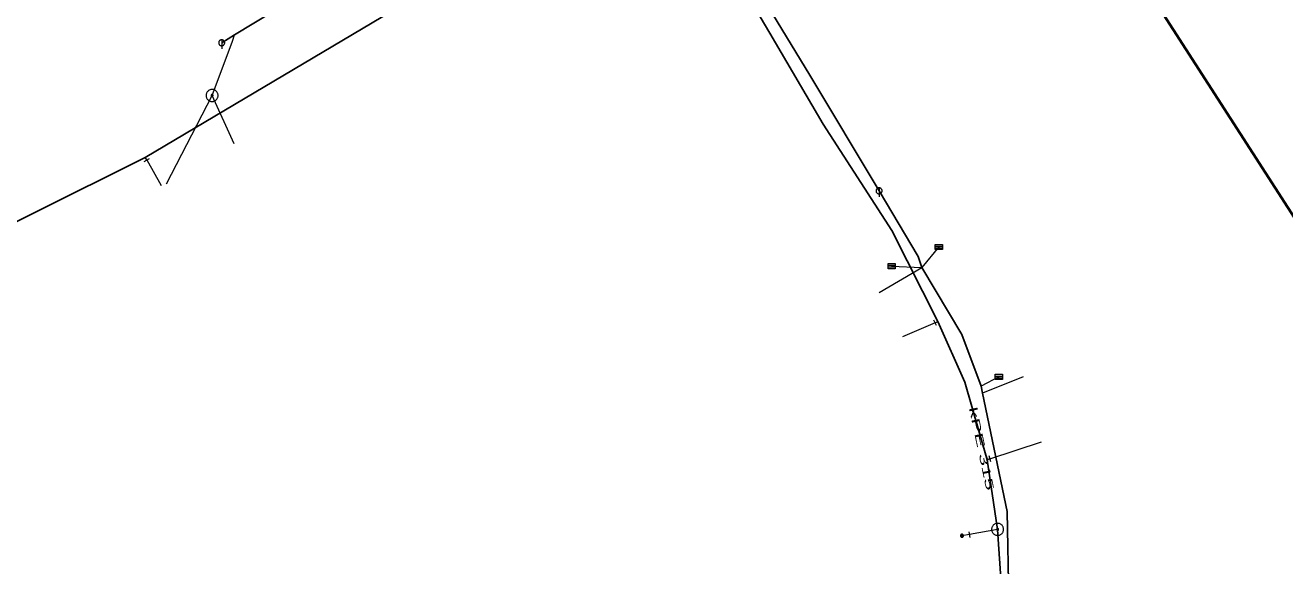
# Model space of a CAD drawing. Extents: x -687468 to -685917, y -974192 to -973456.
# Drawn here: x -686251.8 to -686146.9, y -973639.5 to -973594.5 of the extents above; entities that cross this region are included whole.
import ezdxf
from ezdxf.enums import TextEntityAlignment as Align

# ---------------------------------------------------------------- set-up
doc = ezdxf.new("R2010")
doc.units = 0
doc.header["$LTSCALE"] = 0.27
for name, color, linetype, lineweight in [('1', 7, 'Continuous', 13), ('11', 7, 'Continuous', 13), ('13', 7, 'Continuous', 13), ('14', 7, 'Continuous', 25), ('17', 7, 'Continuous', 25), ('22', 7, 'Continuous', 13), ('31', 7, 'Continuous', 13), ('34', 7, 'Continuous', 13), ('47', 7, 'Continuous', 13), ('9', 7, 'Continuous', 13)]:
    doc.layers.add(name, color=color, linetype=linetype, lineweight=lineweight)

msp = doc.modelspace()

# ---------------------------------------------------------------- linework, layer by layer
at = {"layer": '11'}
for p, q in [((-686240.079, -973607.739), (-686236.269, -973600.389)), ((-686234.43, -973604.42), (-686236.269, -973600.389)), ((-686175.71, -973613), (-686177.129, -973614.719)), ((-686179.649, -973614.59), (-686177.129, -973614.719)), ((-686180.69, -973616.789), (-686177.129, -973614.719)), ((-686170.719, -973623.82), (-686172.17, -973624.579)), ((-686168.67, -973623.809), (-686172.07, -973625.16))]:
    msp.add_line(p, q, dxfattribs=at)
msp.add_lwpolyline([(-686236.269, -973600.389), (-686234.579, -973595.86), (-686234.388, -973595.344)], dxfattribs=at)
at = {"layer": '13'}
for p, q in [((-686241.711, -973605.754), (-686240.51, -973607.879)), ((-686176.022, -973619.312), (-686178.73, -973620.48)), ((-686171.449, -973630.64), (-686167.149, -973629.219))]:
    msp.add_line(p, q, dxfattribs=at)
at = {"layer": '14', "lineweight": 13}
for p, q in [((-686241.711, -973605.754), (-686241.84, -973605.539)), ((-686176.022, -973619.312), (-686175.8, -973619.199)), ((-686171.449, -973630.64), (-686171.69, -973630.71)), ((-686170.809, -973636.51), (-686173.14, -973636.949)), ((-686173.14, -973636.949), (-686173.779, -973637.039))]:
    msp.add_line(p, q, dxfattribs=at)
at = {"layer": '14'}
for points in [[(-686235.469, -973596), (-686234.388, -973595.344), (-686219.48, -973586.316), (-686219.052, -973586.057), (-686200.73, -973574.96), (-686199.012, -973577.618)], [(-686200.73, -973574.96), (-686195.82, -973583.199), (-686189.969, -973592.96), (-686186.46, -973598.699), (-686180.69, -973608.329)], [(-686180.69, -973608.329), (-686177.42, -973613.78), (-686177.129, -973614.719), (-686173.8, -973620.3), (-686172.17, -973624.579), (-686172.07, -973625.16), (-686170.02, -973635.02), (-686169.879, -973642.359)]]:
    msp.add_lwpolyline(points, dxfattribs=at)
at = {"layer": '17', "lineweight": 35}
msp.add_lwpolyline([(-686160.425, -973551.891), (-686169.469, -973574.282), (-686122.999, -973646.384), (-686098.932, -973712.353), (-686089.329, -973782.048), (-686297.791, -974027.806), (-686326.807, -974076.614), (-686379.703, -974100.561), (-686411.584, -974111.413)], dxfattribs=at)
at = {"layer": '17'}
for points in [[(-686198.399, -973580.199), (-686194.62, -973587), (-686189.789, -973595.21), (-686185.35, -973602.78), (-686179.62, -973611.64), (-686175.8, -973619.199), (-686173.53, -973624.27), (-686171.69, -973630.71), (-686170.809, -973636.51)], [(-686215.348, -973589.807), (-686215.489, -973589.889), (-686241.84, -973605.539), (-686260.53, -973614.85), (-686290.159, -973621.799)], [(-686170.809, -973636.51), (-686170.55, -973640.579), (-686170.53, -973645.19), (-686170.789, -973648.34), (-686171.35, -973651.629), (-686172.64, -973657.55), (-686173.609, -973662.11), (-686175.16, -973665.03), (-686175.91, -973666.62), (-686176.82, -973668.219), (-686179.17, -973671.98), (-686179.739, -973673.309), (-686180.87, -973675.1), (-686183.76, -973679.21), (-686188.889, -973684.979)]]:
    msp.add_lwpolyline(points, dxfattribs=at)
at = {"layer": '22'}
for p, q in [((-686235.468, -973595.748), (-686235.469, -973596.492)), ((-686180.689, -973608.077), (-686180.69, -973608.821)), ((-686176.005, -973612.929), (-686175.407, -973612.929)), ((-686176.005, -973613.075), (-686175.407, -973613.075)), ((-686179.944, -973614.519), (-686179.346, -973614.519)), ((-686179.944, -973614.664), (-686179.346, -973614.664)), ((-686171.014, -973623.749), (-686170.416, -973623.749)), ((-686171.014, -973623.894), (-686170.416, -973623.894))]:
    msp.add_line(p, q, dxfattribs=at)
for points in [[(-686235.217, -973596), (-686235.218, -973595.974), (-686235.222, -973595.948), (-686235.228, -973595.922), (-686235.238, -973595.898), (-686235.25, -973595.874), (-686235.264, -973595.852), (-686235.281, -973595.831), (-686235.299, -973595.813), (-686235.32, -973595.796), (-686235.342, -973595.782), (-686235.366, -973595.77), (-686235.39, -973595.76), (-686235.416, -973595.754), (-686235.442, -973595.75), (-686235.468, -973595.748), (-686235.494, -973595.749), (-686235.52, -973595.753), (-686235.546, -973595.759), (-686235.571, -973595.769), (-686235.594, -973595.781), (-686235.616, -973595.795), (-686235.637, -973595.812), (-686235.655, -973595.83), (-686235.672, -973595.851), (-686235.686, -973595.873), (-686235.698, -973595.897), (-686235.708, -973595.921), (-686235.715, -973595.947), (-686235.719, -973595.973), (-686235.721, -973595.999), (-686235.72, -973596.025), (-686235.716, -973596.051), (-686235.709, -973596.077), (-686235.699, -973596.102), (-686235.687, -973596.125), (-686235.673, -973596.147), (-686235.656, -973596.168), (-686235.638, -973596.186), (-686235.617, -973596.203), (-686235.595, -973596.217), (-686235.572, -973596.229), (-686235.547, -973596.239), (-686235.521, -973596.246), (-686235.495, -973596.25), (-686235.469, -973596.252), (-686235.443, -973596.251), (-686235.417, -973596.247), (-686235.391, -973596.24), (-686235.367, -973596.23), (-686235.343, -973596.218), (-686235.321, -973596.204), (-686235.3, -973596.187), (-686235.282, -973596.169), (-686235.265, -973596.148), (-686235.251, -973596.126), (-686235.239, -973596.103), (-686235.229, -973596.078), (-686235.223, -973596.052), (-686235.219, -973596.026)], [(-686180.438, -973608.329), (-686180.439, -973608.303), (-686180.443, -973608.277), (-686180.449, -973608.251), (-686180.459, -973608.227), (-686180.471, -973608.203), (-686180.485, -973608.181), (-686180.502, -973608.16), (-686180.52, -973608.142), (-686180.541, -973608.125), (-686180.563, -973608.111), (-686180.587, -973608.099), (-686180.611, -973608.089), (-686180.637, -973608.083), (-686180.663, -973608.079), (-686180.689, -973608.077), (-686180.715, -973608.078), (-686180.741, -973608.082), (-686180.767, -973608.088), (-686180.792, -973608.098), (-686180.815, -973608.11), (-686180.837, -973608.124), (-686180.858, -973608.141), (-686180.876, -973608.159), (-686180.893, -973608.18), (-686180.907, -973608.202), (-686180.919, -973608.226), (-686180.929, -973608.25), (-686180.936, -973608.276), (-686180.94, -973608.302), (-686180.941, -973608.328), (-686180.941, -973608.354), (-686180.937, -973608.38), (-686180.93, -973608.406), (-686180.92, -973608.431), (-686180.908, -973608.454), (-686180.894, -973608.476), (-686180.877, -973608.497), (-686180.859, -973608.515), (-686180.838, -973608.532), (-686180.816, -973608.546), (-686180.793, -973608.558), (-686180.768, -973608.568), (-686180.742, -973608.575), (-686180.716, -973608.579), (-686180.69, -973608.581), (-686180.664, -973608.58), (-686180.638, -973608.576), (-686180.612, -973608.569), (-686180.588, -973608.559), (-686180.564, -973608.547), (-686180.542, -973608.533), (-686180.521, -973608.516), (-686180.503, -973608.498), (-686180.486, -973608.477), (-686180.472, -973608.455), (-686180.46, -973608.432), (-686180.45, -973608.407), (-686180.444, -973608.381), (-686180.44, -973608.355)], [(-686176.005, -973612.783), (-686175.407, -973612.783), (-686175.407, -973613.22), (-686176.005, -973613.22)], [(-686179.944, -973614.373), (-686179.346, -973614.373), (-686179.346, -973614.809), (-686179.944, -973614.809)], [(-686171.014, -973623.603), (-686170.416, -973623.603), (-686170.416, -973624.039), (-686171.014, -973624.039)]]:
    msp.add_lwpolyline(points, close=True, dxfattribs=at)
at = {"layer": '31'}
for points in [[(-686235.769, -973600.389), (-686235.772, -973600.337), (-686235.78, -973600.284), (-686235.794, -973600.235), (-686235.811, -973600.186), (-686235.836, -973600.139), (-686235.865, -973600.095), (-686235.897, -973600.054), (-686235.934, -973600.017), (-686235.975, -973599.985), (-686236.019, -973599.956), (-686236.066, -973599.931), (-686236.115, -973599.914), (-686236.164, -973599.9), (-686236.217, -973599.892), (-686236.269, -973599.889), (-686236.321, -973599.892), (-686236.373, -973599.9), (-686236.424, -973599.914), (-686236.472, -973599.931), (-686236.519, -973599.956), (-686236.563, -973599.985), (-686236.603, -973600.017), (-686236.641, -973600.054), (-686236.674, -973600.095), (-686236.701, -973600.139), (-686236.726, -973600.186), (-686236.745, -973600.235), (-686236.757, -973600.284), (-686236.766, -973600.337), (-686236.769, -973600.389), (-686236.766, -973600.441), (-686236.757, -973600.493), (-686236.745, -973600.544), (-686236.726, -973600.592), (-686236.701, -973600.639), (-686236.674, -973600.683), (-686236.641, -973600.723), (-686236.603, -973600.761), (-686236.563, -973600.794), (-686236.519, -973600.821), (-686236.472, -973600.846), (-686236.424, -973600.865), (-686236.373, -973600.877), (-686236.321, -973600.886), (-686236.269, -973600.889), (-686236.217, -973600.886), (-686236.164, -973600.877), (-686236.115, -973600.865), (-686236.066, -973600.846), (-686236.019, -973600.821), (-686235.975, -973600.794), (-686235.934, -973600.761), (-686235.897, -973600.723), (-686235.865, -973600.683), (-686235.836, -973600.639), (-686235.811, -973600.592), (-686235.794, -973600.544), (-686235.78, -973600.493), (-686235.772, -973600.441)], [(-686236.186, -973600.389), (-686236.186, -973600.38), (-686236.189, -973600.372), (-686236.191, -973600.364), (-686236.194, -973600.355), (-686236.198, -973600.348), (-686236.203, -973600.341), (-686236.208, -973600.333), (-686236.213, -973600.328), (-686236.221, -973600.323), (-686236.228, -973600.318), (-686236.235, -973600.314), (-686236.244, -973600.311), (-686236.252, -973600.309), (-686236.26, -973600.306), (-686236.269, -973600.306), (-686236.277, -973600.306), (-686236.286, -973600.309), (-686236.294, -973600.311), (-686236.302, -973600.314), (-686236.309, -973600.318), (-686236.316, -973600.323), (-686236.324, -973600.328), (-686236.33, -973600.333), (-686236.336, -973600.341), (-686236.34, -973600.348), (-686236.343, -973600.355), (-686236.347, -973600.364), (-686236.348, -973600.372), (-686236.351, -973600.38), (-686236.351, -973600.389), (-686236.351, -973600.397), (-686236.348, -973600.406), (-686236.347, -973600.414), (-686236.343, -973600.422), (-686236.34, -973600.429), (-686236.336, -973600.436), (-686236.33, -973600.444), (-686236.324, -973600.45), (-686236.316, -973600.456), (-686236.309, -973600.46), (-686236.302, -973600.463), (-686236.294, -973600.467), (-686236.286, -973600.468), (-686236.277, -973600.471), (-686236.269, -973600.471), (-686236.26, -973600.471), (-686236.252, -973600.468), (-686236.244, -973600.467), (-686236.235, -973600.463), (-686236.228, -973600.46), (-686236.221, -973600.456), (-686236.213, -973600.45), (-686236.208, -973600.444), (-686236.203, -973600.436), (-686236.198, -973600.429), (-686236.194, -973600.422), (-686236.191, -973600.414), (-686236.189, -973600.406), (-686236.186, -973600.397)]]:
    msp.add_lwpolyline(points, close=True, dxfattribs=at)
at = {"layer": '34'}
for p, q in [((-686241.924, -973605.88), (-686241.497, -973605.627)), ((-686175.909, -973619.533), (-686176.134, -973619.09)), ((-686171.38, -973630.878), (-686171.517, -973630.401)), ((-686173.093, -973637.192), (-686173.186, -973636.705))]:
    msp.add_line(p, q, dxfattribs=at)
at = {"layer": '47'}
for points in [[(-686170.31, -973636.51), (-686170.313, -973636.458), (-686170.321, -973636.406), (-686170.335, -973636.356), (-686170.353, -973636.307), (-686170.377, -973636.26), (-686170.406, -973636.216), (-686170.439, -973636.176), (-686170.476, -973636.139), (-686170.516, -973636.106), (-686170.56, -973636.077), (-686170.607, -973636.053), (-686170.656, -973636.035), (-686170.706, -973636.021), (-686170.758, -973636.013), (-686170.81, -973636.01), (-686170.862, -973636.013), (-686170.914, -973636.021), (-686170.965, -973636.035), (-686171.013, -973636.053), (-686171.06, -973636.077), (-686171.104, -973636.106), (-686171.145, -973636.139), (-686171.182, -973636.176), (-686171.215, -973636.216), (-686171.243, -973636.26), (-686171.267, -973636.307), (-686171.286, -973636.356), (-686171.299, -973636.406), (-686171.307, -973636.458), (-686171.31, -973636.51), (-686171.307, -973636.562), (-686171.299, -973636.614), (-686171.286, -973636.665), (-686171.267, -973636.713), (-686171.243, -973636.76), (-686171.215, -973636.804), (-686171.182, -973636.845), (-686171.145, -973636.882), (-686171.104, -973636.915), (-686171.06, -973636.943), (-686171.013, -973636.967), (-686170.965, -973636.986), (-686170.914, -973636.999), (-686170.862, -973637.007), (-686170.81, -973637.01), (-686170.758, -973637.007), (-686170.706, -973636.999), (-686170.656, -973636.986), (-686170.607, -973636.967), (-686170.56, -973636.943), (-686170.516, -973636.915), (-686170.476, -973636.882), (-686170.439, -973636.845), (-686170.406, -973636.804), (-686170.377, -973636.76), (-686170.353, -973636.713), (-686170.335, -973636.665), (-686170.321, -973636.614), (-686170.313, -973636.562)], [(-686170.728, -973636.51), (-686170.728, -973636.501), (-686170.73, -973636.493), (-686170.732, -973636.485), (-686170.735, -973636.477), (-686170.739, -973636.469), (-686170.744, -973636.462), (-686170.749, -973636.455), (-686170.755, -973636.449), (-686170.762, -973636.444), (-686170.769, -973636.439), (-686170.777, -973636.435), (-686170.785, -973636.432), (-686170.793, -973636.43), (-686170.801, -973636.428), (-686170.81, -973636.428), (-686170.819, -973636.428), (-686170.827, -973636.43), (-686170.835, -973636.432), (-686170.843, -973636.435), (-686170.851, -973636.439), (-686170.858, -973636.444), (-686170.865, -973636.449), (-686170.871, -973636.455), (-686170.877, -973636.462), (-686170.881, -973636.469), (-686170.885, -973636.477), (-686170.888, -973636.485), (-686170.89, -973636.493), (-686170.892, -973636.501), (-686170.892, -973636.51), (-686170.892, -973636.519), (-686170.89, -973636.527), (-686170.888, -973636.535), (-686170.885, -973636.543), (-686170.881, -973636.551), (-686170.877, -973636.558), (-686170.871, -973636.565), (-686170.865, -973636.571), (-686170.858, -973636.577), (-686170.851, -973636.581), (-686170.843, -973636.585), (-686170.835, -973636.588), (-686170.827, -973636.59), (-686170.819, -973636.592), (-686170.81, -973636.592), (-686170.801, -973636.592), (-686170.793, -973636.59), (-686170.785, -973636.588), (-686170.777, -973636.585), (-686170.769, -973636.581), (-686170.762, -973636.577), (-686170.755, -973636.571), (-686170.749, -973636.565), (-686170.744, -973636.558), (-686170.739, -973636.551), (-686170.735, -973636.543), (-686170.732, -973636.535), (-686170.73, -973636.527), (-686170.728, -973636.519)]]:
    msp.add_lwpolyline(points, close=True, dxfattribs=at)
at = {"layer": '9'}
for points in [[(-686173.652, -973637.039), (-686173.654, -973637.026), (-686173.656, -973637.013), (-686173.659, -973637), (-686173.664, -973636.988), (-686173.669, -973636.976), (-686173.677, -973636.965), (-686173.684, -973636.955), (-686173.695, -973636.945), (-686173.705, -973636.937), (-686173.716, -973636.929), (-686173.728, -973636.924), (-686173.74, -973636.919), (-686173.753, -973636.916), (-686173.766, -973636.914), (-686173.779, -973636.913), (-686173.792, -973636.914), (-686173.804, -973636.916), (-686173.818, -973636.919), (-686173.83, -973636.924), (-686173.842, -973636.929), (-686173.853, -973636.937), (-686173.863, -973636.945), (-686173.873, -973636.955), (-686173.88, -973636.965), (-686173.888, -973636.976), (-686173.894, -973636.988), (-686173.899, -973637), (-686173.902, -973637.013), (-686173.904, -973637.026), (-686173.905, -973637.039), (-686173.904, -973637.052), (-686173.902, -973637.065), (-686173.899, -973637.078), (-686173.894, -973637.09), (-686173.888, -973637.102), (-686173.88, -973637.113), (-686173.873, -973637.123), (-686173.863, -973637.133), (-686173.853, -973637.141), (-686173.842, -973637.148), (-686173.83, -973637.154), (-686173.818, -973637.159), (-686173.804, -973637.162), (-686173.792, -973637.164), (-686173.779, -973637.165), (-686173.766, -973637.164), (-686173.753, -973637.162), (-686173.74, -973637.159), (-686173.728, -973637.154), (-686173.716, -973637.148), (-686173.705, -973637.141), (-686173.695, -973637.133), (-686173.684, -973637.123), (-686173.677, -973637.113), (-686173.669, -973637.102), (-686173.664, -973637.09), (-686173.659, -973637.078), (-686173.656, -973637.065), (-686173.654, -973637.052)], [(-686173.673, -973637.039), (-686173.673, -973637.027), (-686173.674, -973637.017), (-686173.678, -973637.005), (-686173.682, -973636.996), (-686173.687, -973636.986), (-686173.693, -973636.977), (-686173.7, -973636.968), (-686173.708, -973636.96), (-686173.717, -973636.953), (-686173.726, -973636.947), (-686173.736, -973636.942), (-686173.745, -973636.938), (-686173.757, -973636.934), (-686173.767, -973636.933), (-686173.779, -973636.933), (-686173.79, -973636.933), (-686173.801, -973636.934), (-686173.812, -973636.938), (-686173.821, -973636.942), (-686173.831, -973636.947), (-686173.841, -973636.953), (-686173.85, -973636.96), (-686173.858, -973636.968), (-686173.865, -973636.977), (-686173.87, -973636.986), (-686173.875, -973636.996), (-686173.88, -973637.005), (-686173.883, -973637.017), (-686173.885, -973637.027), (-686173.885, -973637.039), (-686173.885, -973637.05), (-686173.883, -973637.061), (-686173.88, -973637.072), (-686173.875, -973637.081), (-686173.87, -973637.092), (-686173.865, -973637.101), (-686173.858, -973637.11), (-686173.85, -973637.118), (-686173.841, -973637.125), (-686173.831, -973637.13), (-686173.821, -973637.136), (-686173.812, -973637.14), (-686173.801, -973637.143), (-686173.79, -973637.145), (-686173.779, -973637.145), (-686173.767, -973637.145), (-686173.757, -973637.143), (-686173.745, -973637.14), (-686173.736, -973637.136), (-686173.726, -973637.13), (-686173.717, -973637.125), (-686173.708, -973637.118), (-686173.7, -973637.11), (-686173.693, -973637.101), (-686173.687, -973637.092), (-686173.682, -973637.081), (-686173.678, -973637.072), (-686173.674, -973637.061), (-686173.673, -973637.05)], [(-686173.691, -973637.039), (-686173.693, -973637.03), (-686173.694, -973637.021), (-686173.696, -973637.012), (-686173.7, -973637.004), (-686173.704, -973636.996), (-686173.709, -973636.988), (-686173.715, -973636.981), (-686173.721, -973636.975), (-686173.728, -973636.969), (-686173.736, -973636.964), (-686173.744, -973636.96), (-686173.752, -973636.956), (-686173.761, -973636.954), (-686173.77, -973636.953), (-686173.779, -973636.951), (-686173.788, -973636.953), (-686173.797, -973636.954), (-686173.806, -973636.956), (-686173.814, -973636.96), (-686173.821, -973636.964), (-686173.83, -973636.969), (-686173.837, -973636.975), (-686173.843, -973636.981), (-686173.848, -973636.988), (-686173.853, -973636.996), (-686173.858, -973637.004), (-686173.861, -973637.012), (-686173.864, -973637.021), (-686173.865, -973637.03), (-686173.866, -973637.039), (-686173.865, -973637.048), (-686173.864, -973637.057), (-686173.861, -973637.066), (-686173.858, -973637.074), (-686173.853, -973637.081), (-686173.848, -973637.09), (-686173.843, -973637.097), (-686173.837, -973637.103), (-686173.83, -973637.108), (-686173.821, -973637.114), (-686173.814, -973637.118), (-686173.806, -973637.121), (-686173.797, -973637.124), (-686173.788, -973637.125), (-686173.779, -973637.126), (-686173.77, -973637.125), (-686173.761, -973637.124), (-686173.752, -973637.121), (-686173.744, -973637.118), (-686173.736, -973637.114), (-686173.728, -973637.108), (-686173.721, -973637.103), (-686173.715, -973637.097), (-686173.709, -973637.09), (-686173.704, -973637.081), (-686173.7, -973637.074), (-686173.696, -973637.066), (-686173.694, -973637.057), (-686173.693, -973637.048)], [(-686173.712, -973637.039), (-686173.712, -973637.032), (-686173.714, -973637.025), (-686173.715, -973637.018), (-686173.718, -973637.012), (-686173.721, -973637.005), (-686173.725, -973637), (-686173.728, -973636.994), (-686173.733, -973636.989), (-686173.74, -973636.985), (-686173.745, -973636.981), (-686173.752, -973636.978), (-686173.758, -973636.975), (-686173.765, -973636.974), (-686173.772, -973636.972), (-686173.779, -973636.972), (-686173.786, -973636.972), (-686173.793, -973636.974), (-686173.799, -973636.975), (-686173.806, -973636.978), (-686173.813, -973636.981), (-686173.818, -973636.985), (-686173.824, -973636.989), (-686173.829, -973636.994), (-686173.833, -973637), (-686173.837, -973637.005), (-686173.84, -973637.012), (-686173.843, -973637.018), (-686173.845, -973637.025), (-686173.846, -973637.032), (-686173.846, -973637.039), (-686173.846, -973637.046), (-686173.845, -973637.053), (-686173.843, -973637.059), (-686173.84, -973637.066), (-686173.837, -973637.073), (-686173.833, -973637.078), (-686173.829, -973637.084), (-686173.824, -973637.089), (-686173.818, -973637.093), (-686173.813, -973637.097), (-686173.806, -973637.1), (-686173.799, -973637.103), (-686173.793, -973637.105), (-686173.786, -973637.106), (-686173.779, -973637.106), (-686173.772, -973637.106), (-686173.765, -973637.105), (-686173.758, -973637.103), (-686173.752, -973637.1), (-686173.745, -973637.097), (-686173.74, -973637.093), (-686173.733, -973637.089), (-686173.728, -973637.084), (-686173.725, -973637.078), (-686173.721, -973637.073), (-686173.718, -973637.066), (-686173.715, -973637.059), (-686173.714, -973637.053), (-686173.712, -973637.046)], [(-686173.732, -973637.039), (-686173.732, -973637.034), (-686173.733, -973637.029), (-686173.733, -973637.024), (-686173.736, -973637.02), (-686173.738, -973637.015), (-686173.741, -973637.011), (-686173.744, -973637.008), (-686173.748, -973637.004), (-686173.75, -973637.001), (-686173.755, -973636.998), (-686173.76, -973636.996), (-686173.764, -973636.994), (-686173.769, -973636.993), (-686173.774, -973636.992), (-686173.779, -973636.992), (-686173.784, -973636.992), (-686173.789, -973636.993), (-686173.794, -973636.994), (-686173.798, -973636.996), (-686173.803, -973636.998), (-686173.807, -973637.001), (-686173.811, -973637.004), (-686173.814, -973637.008), (-686173.816, -973637.011), (-686173.82, -973637.015), (-686173.821, -973637.02), (-686173.824, -973637.024), (-686173.825, -973637.029), (-686173.826, -973637.034), (-686173.826, -973637.039), (-686173.826, -973637.044), (-686173.825, -973637.049), (-686173.824, -973637.054), (-686173.821, -973637.058), (-686173.82, -973637.063), (-686173.816, -973637.067), (-686173.814, -973637.071), (-686173.811, -973637.074), (-686173.807, -973637.076), (-686173.803, -973637.08), (-686173.798, -973637.081), (-686173.794, -973637.084), (-686173.789, -973637.085), (-686173.784, -973637.086), (-686173.779, -973637.086), (-686173.774, -973637.086), (-686173.769, -973637.085), (-686173.764, -973637.084), (-686173.76, -973637.081), (-686173.755, -973637.08), (-686173.75, -973637.076), (-686173.748, -973637.074), (-686173.744, -973637.071), (-686173.741, -973637.067), (-686173.738, -973637.063), (-686173.736, -973637.058), (-686173.733, -973637.054), (-686173.733, -973637.049), (-686173.732, -973637.044)], [(-686173.752, -973637.039), (-686173.752, -973637.036), (-686173.752, -973637.032), (-686173.753, -973637.031), (-686173.754, -973637.027), (-686173.755, -973637.025), (-686173.757, -973637.023), (-686173.759, -973637.021), (-686173.761, -973637.019), (-686173.763, -973637.017), (-686173.765, -973637.015), (-686173.767, -973637.014), (-686173.771, -973637.013), (-686173.772, -973637.012), (-686173.776, -973637.012), (-686173.779, -973637.012), (-686173.782, -973637.012), (-686173.785, -973637.012), (-686173.788, -973637.013), (-686173.79, -973637.014), (-686173.793, -973637.015), (-686173.794, -973637.017), (-686173.798, -973637.019), (-686173.799, -973637.021), (-686173.801, -973637.023), (-686173.803, -973637.025), (-686173.804, -973637.027), (-686173.804, -973637.031), (-686173.806, -973637.032), (-686173.806, -973637.036), (-686173.807, -973637.039), (-686173.806, -973637.042), (-686173.806, -973637.045), (-686173.804, -973637.048), (-686173.804, -973637.05), (-686173.803, -973637.053), (-686173.801, -973637.054), (-686173.799, -973637.058), (-686173.798, -973637.059), (-686173.794, -973637.061), (-686173.793, -973637.063), (-686173.79, -973637.064), (-686173.788, -973637.065), (-686173.785, -973637.066), (-686173.782, -973637.066), (-686173.779, -973637.067), (-686173.776, -973637.066), (-686173.772, -973637.066), (-686173.771, -973637.065), (-686173.767, -973637.064), (-686173.765, -973637.063), (-686173.763, -973637.061), (-686173.761, -973637.059), (-686173.759, -973637.058), (-686173.757, -973637.054), (-686173.755, -973637.053), (-686173.754, -973637.05), (-686173.753, -973637.048), (-686173.752, -973637.045), (-686173.752, -973637.042)], [(-686173.771, -973637.039), (-686173.771, -973637.038), (-686173.771, -973637.037), (-686173.772, -973637.037), (-686173.772, -973637.036), (-686173.772, -973637.035), (-686173.772, -973637.034), (-686173.772, -973637.034), (-686173.774, -973637.032), (-686173.774, -973637.032), (-686173.775, -973637.032), (-686173.776, -973637.032), (-686173.777, -973637.032), (-686173.777, -973637.031), (-686173.777, -973637.031), (-686173.779, -973637.031), (-686173.78, -973637.031), (-686173.781, -973637.031), (-686173.781, -973637.032), (-686173.782, -973637.032), (-686173.782, -973637.032), (-686173.784, -973637.032), (-686173.784, -973637.032), (-686173.785, -973637.034), (-686173.785, -973637.034), (-686173.786, -973637.035), (-686173.786, -973637.036), (-686173.787, -973637.037), (-686173.787, -973637.037), (-686173.787, -973637.038), (-686173.787, -973637.039), (-686173.787, -973637.04), (-686173.787, -973637.041), (-686173.787, -973637.041), (-686173.786, -973637.042), (-686173.786, -973637.043), (-686173.785, -973637.044), (-686173.785, -973637.044), (-686173.784, -973637.045), (-686173.784, -973637.045), (-686173.782, -973637.046), (-686173.782, -973637.046), (-686173.781, -973637.047), (-686173.781, -973637.047), (-686173.78, -973637.047), (-686173.779, -973637.047), (-686173.777, -973637.047), (-686173.777, -973637.047), (-686173.777, -973637.047), (-686173.776, -973637.046), (-686173.775, -973637.046), (-686173.774, -973637.045), (-686173.774, -973637.045), (-686173.772, -973637.044), (-686173.772, -973637.044), (-686173.772, -973637.043), (-686173.772, -973637.042), (-686173.772, -973637.041), (-686173.771, -973637.041), (-686173.771, -973637.04)]]:
    msp.add_lwpolyline(points, close=True, dxfattribs=at)

# ---------------------------------------------------------------- texts
at = {"layer": '1', "width": 2.1}
msp.add_text('kPE 315 ', height=0.6667, rotation=282, dxfattribs=at).set_placement((-686172.419, -973630.113), align=Align.CENTER)

doc.saveas('drawing.dxf')
